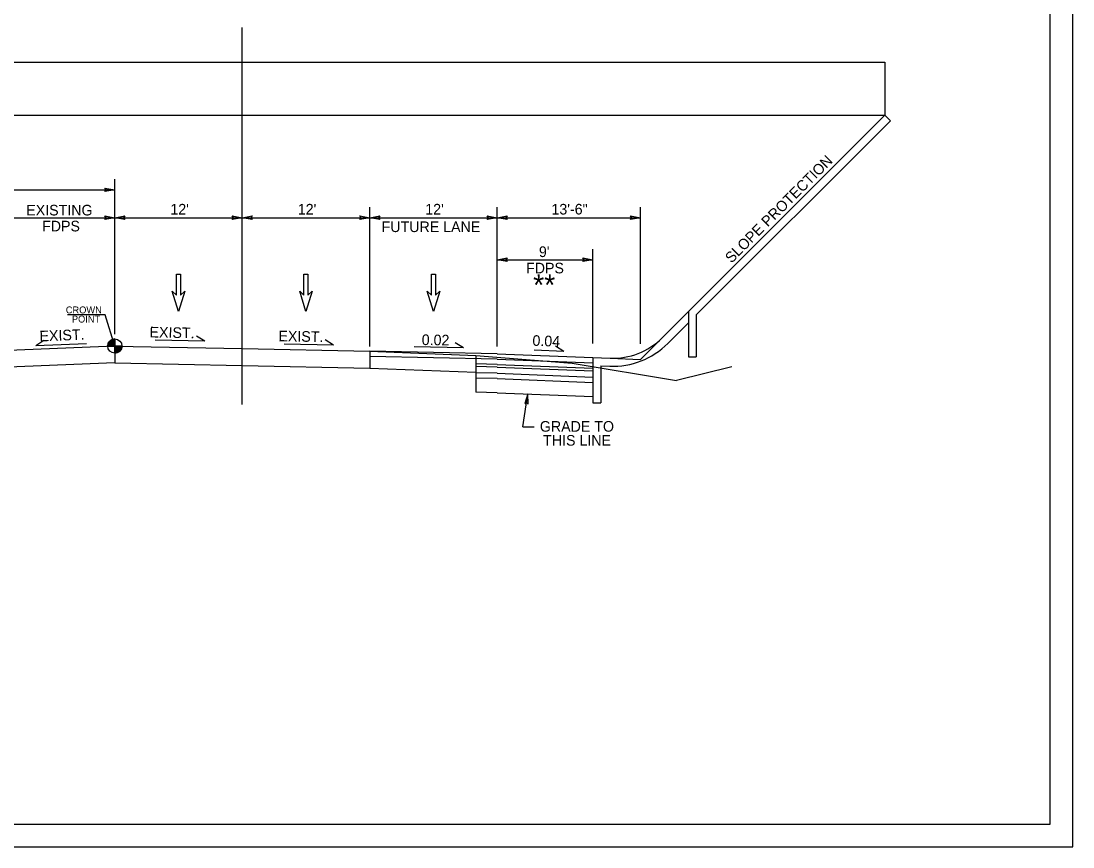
# Model space of a CAD drawing. Extents: x 1553195 to 1553792, y 810516 to 810787.
# Drawn here: x 1553567 to 1553666, y 810629 to 810706.7 of the extents above; entities that cross this region are included whole.
import ezdxf

# ---------------------------------------------------------------- set-up
doc = ezdxf.new("R2010")
doc.units = 0
for name, color, linetype in [('Old_Level_11', 7, 'Continuous'), ('Prop Dimension', 7, 'Continuous'), ('Prop DSN Text', 7, 'Continuous'), ('Prop Pavement Schedule Description CELL', 7, 'Continuous'), ('Prop Terminator CELL', 7, 'Continuous'), ('Prop Typical Section', 7, 'Continuous'), ('Sheet Plan CELL', 7, 'Continuous'), ('Typical Arrow Superelevation CELL', 7, 'Continuous'), ('Typical Grade Point Symbol CELL', 7, 'Continuous'), ('Typical Pavement Slope CELL', 7, 'Continuous'), ('Typical Text ID Circle CELL', 7, 'Continuous'), ('z - Construction', 7, 'Continuous')]:
    doc.layers.add(name, color=color, linetype=linetype)

msp = doc.modelspace()

# ---------------------------------------------------------------- linework, layer by layer
at = {"layer": 'Old_Level_11'}
for p, q in [((1553575.159, 810676.146), (1553575.83, 810676.146)), ((1553575.83, 810676.146), (1553575.83, 810676.817)), ((1553575.831, 810675.474), (1553575.83, 810676.146)), ((1553576.501, 810676.146), (1553575.83, 810676.146)), ((1553575.83, 810676.146), (1553575.831, 810675.474))]:
    msp.add_line(p, q, dxfattribs=at)
for points in [[(1553575.166, 810676.241), (1553575.166, 810676.146)], [(1553575.179, 810676.31), (1553575.179, 810676.146)], [(1553575.193, 810676.356), (1553575.193, 810676.146)], [(1553575.206, 810676.393), (1553575.206, 810676.146)], [(1553575.22, 810676.425), (1553575.22, 810676.146)], [(1553575.233, 810676.453), (1553575.233, 810676.146)], [(1553575.247, 810676.477), (1553575.247, 810676.146)], [(1553575.26, 810676.499), (1553575.26, 810676.146)], [(1553575.273, 810676.52), (1553575.273, 810676.146)], [(1553575.287, 810676.54), (1553575.287, 810676.146)], [(1553575.3, 810676.557), (1553575.3, 810676.146)], [(1553575.314, 810676.574), (1553575.314, 810676.146)], [(1553575.327, 810676.59), (1553575.327, 810676.146)], [(1553575.341, 810676.605), (1553575.341, 810676.146)], [(1553575.354, 810676.619), (1553575.354, 810676.146)], [(1553575.367, 810676.632), (1553575.367, 810676.146)], [(1553575.381, 810676.644), (1553575.381, 810676.146)], [(1553575.394, 810676.656), (1553575.394, 810676.146)], [(1553575.408, 810676.668), (1553575.408, 810676.146)], [(1553575.421, 810676.678), (1553575.421, 810676.146)], [(1553575.435, 810676.687), (1553575.435, 810676.146)], [(1553575.448, 810676.698), (1553575.448, 810676.146)], [(1553575.461, 810676.707), (1553575.461, 810676.146)], [(1553575.475, 810676.716), (1553575.475, 810676.146)], [(1553575.488, 810676.723), (1553575.488, 810676.146)], [(1553575.502, 810676.731), (1553575.502, 810676.146)], [(1553575.515, 810676.738), (1553575.515, 810676.146)], [(1553575.529, 810676.745), (1553575.529, 810676.146)], [(1553575.542, 810676.751), (1553575.542, 810676.146)], [(1553575.555, 810676.757), (1553575.555, 810676.146)], [(1553575.569, 810676.763), (1553575.569, 810676.146)], [(1553575.582, 810676.769), (1553575.582, 810676.146)], [(1553575.596, 810676.775), (1553575.596, 810676.146)], [(1553575.609, 810676.78), (1553575.609, 810676.146)], [(1553575.623, 810676.784), (1553575.623, 810676.146)], [(1553575.636, 810676.789), (1553575.636, 810676.146)], [(1553575.649, 810676.792), (1553575.649, 810676.146)], [(1553575.663, 810676.796), (1553575.663, 810676.146)], [(1553575.676, 810676.799), (1553575.676, 810676.146)], [(1553575.69, 810676.802), (1553575.69, 810676.146)], [(1553575.703, 810676.805), (1553575.703, 810676.146)], [(1553575.717, 810676.808), (1553575.717, 810676.146)], [(1553575.73, 810676.81), (1553575.73, 810676.146)], [(1553575.743, 810676.811), (1553575.743, 810676.146)], [(1553575.757, 810676.813), (1553575.757, 810676.146)], [(1553575.77, 810676.814), (1553575.77, 810676.146)], [(1553575.784, 810676.816), (1553575.784, 810676.146)], [(1553575.797, 810676.816), (1553575.797, 810676.146)], [(1553575.811, 810676.817), (1553575.811, 810676.146)], [(1553575.824, 810676.817), (1553575.824, 810676.817), (1553575.824, 810676.146)], [(1553575.84, 810676.146), (1553575.84, 810675.474), (1553575.84, 810675.474)], [(1553575.854, 810676.146), (1553575.854, 810675.474)], [(1553575.867, 810676.146), (1553575.867, 810675.476)], [(1553575.881, 810676.146), (1553575.881, 810675.476)], [(1553575.894, 810676.146), (1553575.894, 810675.477)], [(1553575.908, 810676.146), (1553575.908, 810675.479)], [(1553575.921, 810676.146), (1553575.921, 810675.48)], [(1553575.934, 810676.146), (1553575.934, 810675.483)], [(1553575.948, 810676.146), (1553575.948, 810675.485)], [(1553575.961, 810676.146), (1553575.961, 810675.488)], [(1553575.975, 810676.146), (1553575.975, 810675.491)], [(1553575.988, 810676.146), (1553575.988, 810675.494)], [(1553576.002, 810676.146), (1553576.002, 810675.497)], [(1553576.015, 810676.146), (1553576.015, 810675.501)], [(1553576.028, 810676.146), (1553576.028, 810675.504)], [(1553576.042, 810676.146), (1553576.042, 810675.509)], [(1553576.055, 810676.146), (1553576.055, 810675.513)], [(1553576.069, 810676.146), (1553576.069, 810675.518)], [(1553576.082, 810676.146), (1553576.082, 810675.524)], [(1553576.095, 810676.146), (1553576.095, 810675.529)], [(1553576.109, 810676.146), (1553576.109, 810675.535)], [(1553576.122, 810676.146), (1553576.122, 810675.541)], [(1553576.136, 810676.146), (1553576.136, 810675.547)], [(1553576.149, 810676.146), (1553576.149, 810675.555)], [(1553576.163, 810676.146), (1553576.163, 810675.562)], [(1553576.176, 810676.146), (1553576.176, 810675.57)], [(1553576.19, 810676.146), (1553576.19, 810675.579)], [(1553576.203, 810676.146), (1553576.203, 810675.588)], [(1553576.216, 810676.146), (1553576.216, 810675.597)], [(1553576.23, 810676.146), (1553576.23, 810675.606)], [(1553576.243, 810676.146), (1553576.243, 810675.616)], [(1553576.257, 810676.146), (1553576.257, 810675.626)], [(1553576.27, 810676.146), (1553576.27, 810675.638)], [(1553576.284, 810676.146), (1553576.284, 810675.65)], [(1553576.297, 810676.146), (1553576.297, 810675.662)], [(1553576.31, 810676.146), (1553576.31, 810675.676)], [(1553576.324, 810676.146), (1553576.324, 810675.691)], [(1553576.337, 810676.146), (1553576.337, 810675.706)], [(1553576.351, 810676.146), (1553576.351, 810675.722)], [(1553576.364, 810676.146), (1553576.364, 810675.738)], [(1553576.377, 810676.146), (1553576.377, 810675.756)], [(1553576.391, 810676.146), (1553576.391, 810675.776)], [(1553576.404, 810676.146), (1553576.404, 810675.797)], [(1553576.418, 810676.146), (1553576.418, 810675.82)], [(1553576.431, 810676.146), (1553576.431, 810675.846)], [(1553576.445, 810676.146), (1553576.445, 810675.874)], [(1553576.458, 810676.146), (1553576.458, 810675.905)], [(1553576.472, 810676.146), (1553576.472, 810675.946)], [(1553576.485, 810676.146), (1553576.485, 810675.993)], [(1553576.498, 810676.146), (1553576.498, 810676.073)]]:
    msp.add_lwpolyline(points, dxfattribs=at)
msp.add_circle((1553575.831, 810676.146), 0.671, dxfattribs=at)
for start, end in [(90.00952, 180.00952), (270.00952, 0.00952)]:
    msp.add_arc((1553575.831, 810676.146), 0.671, start, end, dxfattribs=at)
at = {"layer": 'Prop Dimension'}
for p, q in [((1553584.297, 810676.61), (1553583.514, 810677.083)), ((1553568.39, 810676.213), (1553569.163, 810676.702)), ((1553568.39, 810676.213), (1553573.174, 810676.405)), ((1553584.297, 810676.61), (1553579.637, 810676.703)), ((1553596.428, 810676.248), (1553591.768, 810676.342)), ((1553596.428, 810676.248), (1553595.645, 810676.722)), ((1553608.663, 810675.982), (1553604.003, 810676.075)), ((1553608.663, 810675.982), (1553607.88, 810676.455)), ((1553618.112, 810675.643), (1553617.338, 810676.132)), ((1553618.112, 810675.643), (1553615.317, 810675.755))]:
    msp.add_line(p, q, dxfattribs=at)
at = {"layer": 'Prop DSN Text'}
for points in [[(1553574.893, 810691.019), (1553575.831, 810690.858), (1553574.888, 810690.691), (1553575.008, 810690.858)], [(1553574.893, 810688.395), (1553575.831, 810688.233), (1553574.888, 810688.066), (1553575.008, 810688.233)], [(1553576.768, 810688.072), (1553575.831, 810688.233), (1553576.773, 810688.4), (1553576.654, 810688.233)], [(1553586.893, 810688.395), (1553587.831, 810688.233), (1553586.888, 810688.066), (1553587.008, 810688.233)], [(1553588.768, 810688.072), (1553587.831, 810688.233), (1553588.773, 810688.4), (1553588.654, 810688.233)], [(1553598.893, 810688.395), (1553599.831, 810688.233), (1553598.888, 810688.066), (1553599.008, 810688.233)], [(1553600.768, 810688.072), (1553599.831, 810688.233), (1553600.773, 810688.4), (1553600.654, 810688.233)], [(1553610.893, 810688.395), (1553611.831, 810688.233), (1553610.888, 810688.066), (1553611.008, 810688.233)], [(1553612.768, 810688.072), (1553611.831, 810688.233), (1553612.773, 810688.4), (1553612.654, 810688.233)], [(1553624.393, 810688.395), (1553625.331, 810688.233), (1553624.388, 810688.066), (1553624.508, 810688.233)], [(1553612.768, 810684.12), (1553611.831, 810684.281), (1553612.773, 810684.448), (1553612.654, 810684.281)], [(1553619.893, 810684.442), (1553620.831, 810684.281), (1553619.888, 810684.114), (1553620.008, 810684.281)], [(1553614.748, 810670.692), (1553614.729, 810671.643), (1553614.423, 810670.736), (1553614.606, 810670.83)]]:
    msp.add_lwpolyline(points, close=True, dxfattribs=at)
at = {"layer": 'Prop Pavement Schedule Description CELL'}
for p, q in [((1553625.331, 810676.372), (1553625.331, 810689.233)), ((1553620.831, 810676.381), (1553620.831, 810685.281)), ((1553614.261, 810668.558), (1553614.729, 810671.643)), ((1553614.261, 810668.558), (1553615.322, 810668.558))]:
    msp.add_line(p, q, dxfattribs=at)
at = {"layer": 'Prop Terminator CELL'}
msp.add_lwpolyline([(1553663.906, 810631.126), (1553663.906, 810784.388), (1553424.506, 810784.388), (1553424.506, 810631.126)], close=True, dxfattribs=at)
at = {"layer": 'Prop Typical Section'}
msp.add_line((1553587.831, 810670.66), (1553587.831, 810706.132), dxfattribs=at)
for points in [[(1553581.237, 810681.307), (1553581.643, 810680.932), (1553581.643, 810682.932), (1553582.018, 810682.932), (1553582.018, 810680.932), (1553582.424, 810681.307), (1553581.831, 810679.401)], [(1553581.237, 810681.307), (1553581.643, 810680.932), (1553581.643, 810682.932), (1553582.018, 810682.932), (1553582.018, 810680.932), (1553582.424, 810681.307), (1553581.831, 810679.401)], [(1553593.237, 810681.307), (1553593.643, 810680.932), (1553593.643, 810682.932), (1553594.018, 810682.932), (1553594.018, 810680.932), (1553594.424, 810681.307), (1553593.831, 810679.401)], [(1553593.237, 810681.307), (1553593.643, 810680.932), (1553593.643, 810682.932), (1553594.018, 810682.932), (1553594.018, 810680.932), (1553594.424, 810681.307), (1553593.831, 810679.401)], [(1553605.237, 810681.307), (1553605.643, 810680.932), (1553605.643, 810682.932), (1553606.018, 810682.932), (1553606.018, 810680.932), (1553606.424, 810681.307), (1553605.831, 810679.401)]]:
    msp.add_lwpolyline(points, close=True, dxfattribs=at)
at = {"layer": 'Sheet Plan CELL'}
msp.add_lwpolyline([(1553666.043, 810628.988), (1553666.043, 810786.526), (1553422.368, 810786.526), (1553422.368, 810628.988)], close=True, dxfattribs=at)
at = {"layer": 'Typical Arrow Superelevation CELL'}
for p, q in [((1553443.33, 810702.889), (1553648.332, 810702.889)), ((1553648.332, 810702.889), (1553648.332, 810697.889)), ((1553443.33, 810697.889), (1553648.332, 810697.889)), ((1553627.364, 810676.921), (1553648.332, 810697.889)), ((1553648.332, 810697.889), (1553648.862, 810697.359)), ((1553630.581, 810679.077), (1553648.862, 810697.359)), ((1553629.831, 810679.388), (1553629.831, 810675.146)), ((1553630.581, 810679.077), (1553630.581, 810675.146)), ((1553627.894, 810676.391), (1553629.831, 810678.327)), ((1553625.331, 810674.888), (1553627.364, 810676.921)), ((1553620.831, 810675.066), (1553622.457, 810675.002)), ((1553620.831, 810675.066), (1553620.831, 810670.81)), ((1553622.457, 810675.002), (1553625.331, 810674.888)), ((1553629.831, 810675.146), (1553630.581, 810675.146)), ((1553621.581, 810674.286), (1553622.428, 810674.252)), ((1553621.581, 810674.286), (1553621.581, 810670.81)), ((1553620.831, 810670.81), (1553621.581, 810670.81))]:
    msp.add_line(p, q, dxfattribs=at)
for radius in [7.322, 6.572]:
    msp.add_arc((1553622.717, 810681.568), radius, 267.73793, 315, dxfattribs=at)
at = {"layer": 'Typical Grade Point Symbol CELL'}
for p, q in [((1553575.831, 810676.146), (1553565.831, 810675.746)), ((1553575.831, 810676.146), (1553587.831, 810675.906)), ((1553575.831, 810676.146), (1553575.831, 810674.561)), ((1553587.831, 810675.906), (1553599.831, 810675.666)), ((1553599.831, 810675.666), (1553609.831, 810675.266)), ((1553599.831, 810675.666), (1553599.831, 810674.081)), ((1553609.831, 810675.266), (1553609.831, 810673.681)), ((1553609.831, 810675.266), (1553618.877, 810674.542)), ((1553575.831, 810674.561), (1553565.831, 810674.161)), ((1553575.831, 810674.561), (1553587.831, 810674.321)), ((1553587.831, 810674.321), (1553599.831, 810674.081)), ((1553599.831, 810674.081), (1553609.831, 810673.681)), ((1553618.877, 810674.542), (1553628.704, 810672.904)), ((1553633.915, 810674.207), (1553628.704, 810672.904))]:
    msp.add_line(p, q, dxfattribs=at)
at = {"layer": 'Typical Pavement Slope CELL'}
for p, q in [((1553611.831, 810675.426), (1553599.831, 810675.666)), ((1553611.831, 810674.926), (1553599.831, 810675.166)), ((1553611.831, 810675.426), (1553620.831, 810675.066)), ((1553611.831, 810674.426), (1553609.831, 810674.466)), ((1553611.831, 810674.176), (1553609.831, 810674.216)), ((1553611.831, 810674.926), (1553620.831, 810674.566)), ((1553611.831, 810674.426), (1553620.831, 810674.066)), ((1553611.831, 810674.176), (1553620.831, 810673.816)), ((1553609.831, 810673.681), (1553609.831, 810671.799)), ((1553611.831, 810673.592), (1553609.831, 810673.632)), ((1553611.831, 810673.092), (1553609.831, 810673.132)), ((1553611.831, 810673.592), (1553620.831, 810673.232)), ((1553611.831, 810673.092), (1553620.831, 810672.732)), ((1553611.831, 810671.759), (1553609.831, 810671.799)), ((1553611.831, 810671.759), (1553620.831, 810671.399))]:
    msp.add_line(p, q, dxfattribs=at)
at = {"layer": 'Typical Text ID Circle CELL'}
msp.add_lwpolyline([(1553575.831, 810676.146), (1553574.927, 810679.1), (1553571.389, 810679.1)], dxfattribs=at)
at = {"layer": 'z - Construction'}
for p, q in [((1553575.831, 810677.256), (1553575.831, 810691.858)), ((1553545.831, 810690.858), (1553575.831, 810690.858)), ((1553599.831, 810676.111), (1553599.831, 810689.233)), ((1553611.831, 810676.111), (1553611.831, 810689.233)), ((1553565.831, 810688.233), (1553575.831, 810688.233)), ((1553575.831, 810688.233), (1553587.831, 810688.233)), ((1553587.831, 810688.233), (1553599.831, 810688.233)), ((1553599.831, 810688.233), (1553611.831, 810688.233)), ((1553611.831, 810688.233), (1553625.331, 810688.233)), ((1553611.831, 810684.281), (1553620.831, 810684.281))]:
    msp.add_line(p, q, dxfattribs=at)

# ---------------------------------------------------------------- texts
at = {"layer": 'Prop Pavement Schedule Description CELL'}
for s, rotation, p in [('SLOPE PROTECTION', 45, (1553633.89, 810683.889)), ('EXIST.', 358.85413, (1553579.095, 810676.965)), ('EXIST.', 2.29061, (1553568.759, 810676.581)), ('EXIST.', 358.85413, (1553591.226, 810676.603)), ('0.02', 358.85413, (1553604.721, 810676.252)), ('0.04', 357.70939, (1553615.137, 810676.18))]:
    msp.add_text(s, height=1, rotation=rotation, dxfattribs=at).set_placement(p)
for s, height, p in [('EXISTING', 1, (1553567.494, 810688.445)), ("12'", 1, (1553581.062, 810688.534)), ("12'", 1, (1553593.062, 810688.534)), ("12'", 1, (1553605.062, 810688.534)), ('13\'-6"', 1, (1553616.943, 810688.534)), ('FDPS', 1, (1553568.982, 810686.944)), ('FUTURE LANE', 1, (1553600.953, 810686.881)), ("9'", 1, (1553615.76, 810684.529)), ('FDPS', 1, (1553614.551, 810682.992)), ('**', 2, (1553615.218, 810680.906)), ('GRADE TO ', 1, (1553615.849, 810668.085)), ('THIS LINE', 1, (1553616.16, 810666.774))]:
    msp.add_text(s, height=height, dxfattribs=at).set_placement(p)
at = {"layer": 'Typical Text ID Circle CELL'}
for s, p in [('CROWN', (1553571.215, 810679.222)), ('POINT', (1553571.789, 810678.364))]:
    msp.add_text(s, height=0.6525, dxfattribs=at).set_placement(p)

doc.saveas('drawing.dxf')
